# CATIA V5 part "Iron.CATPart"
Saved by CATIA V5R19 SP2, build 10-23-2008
Part number: Part1
Bounding box of the stored display mesh (mm): x -79.133 to 79.133, y -300 to 0, z -3.106 to 127.728
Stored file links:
  C:\Users\SAMAD\Desktop\shape2.CATPart
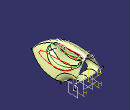
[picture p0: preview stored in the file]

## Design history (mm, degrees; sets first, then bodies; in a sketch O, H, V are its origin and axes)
Body1 (main body)
  Sketch1 on zx-plane, origin (0, 0, 0), H (-1, 0, 0), V (0, 0, 1)
    point P1 (70, 0)
    arc A1 centre (-241.0845, -75.0096) radius 320 from (70, 0) to (20.4309, 109.4076) ccw
    arc A2 centre (0, 95) radius 25 from (20.4309, 109.4076) to (-20.4309, 109.4076) ccw
    point P4 (0, 95)
    arc A3 centre (241.0845, -75.0096) radius 320 from (-20.4309, 109.4076) to (-70, 0) ccw
    point P7 (-70, 0)
    distance A2 H = 120
    distance P1 V = 70
    radius A2 = 25
    radius A1 = 320
    coincidence: P1 H, P7 H, P4 V
    tangency: A2 A1, A3 A2
    symmetry: A1 A3 V
  Sketch2 on yz-plane, origin (0, 0, 0), H (0, 1, 0), V (0, 0, 1)
    spline S1 through (0, 120) (-97.5385, 126.0039) (-300, 0)
    point P1 (0, 120)
    point P2 (-300, 0)
    distance P2 V = 300
    distance P1 H = 120
    coincidence: P1 V, P2 H
  Sketch3 on xy-plane, origin (0, 0, 0), H (1, 0, 0), V (0, 1, 0)
    spline S1 through (70, 0) (71.6167, -27.0715) (76.454, -63.6062) (62.9919, -184.814) (0, -300)
    reference projected point E1 (70, 0) from Sketch1.P7
    reference projected point E2 (0, -300) from Sketch2.P2
    point P1 (70, 0)
    point P2 (0, -300)
    coincidence: P1 H, P2 V, P1 E1, E2 P2
  Symmetry1: ToTransfor Sketch3, Reference yz-plane
  Sketch4 on xy-plane, origin (0, 0, 0), H (1, 0, 0), V (0, 1, 0)
    line L1 (0, 0) -> (0, -300.4665)
    vertical: L1 V
  Plane1: type Offset, RefPlane zx-plane, Offset -214
  Intersect1: ToIntersect1 Plane1, ToIntersect2 Sketch3
  Intersect2: ToIntersect1 Plane1, ToIntersect2 Sketch4
  Intersect3: ToIntersect1 Symmetry1, ToIntersect2 Plane1
  Intersect4: ToIntersect1 Sketch2, ToIntersect2 Plane1
  Sketch5 on Plane1, origin (0, -214, 0), H (-1, 0, 0), V (0, 0, 1)
    point P1 (-50.9944, 0)
    arc A1 centre (133.4907, -45.4446) radius 190 from (-50.9944, 0) to (-12.275, 76.4255) cw
    arc A2 centre (0, 66.1628) radius 16 from (-12.275, 76.4255) to (12.275, 76.4255) cw
    point P4 (0, 66.1628)
    arc A3 centre (-133.4907, -45.4446) radius 190 from (12.275, 76.4255) to (50.9944, 0) cw
    point P7 (50.9944, 0)
    reference projected point E1 (-50.9944, 0) from Intersect1
    reference projected point E2 (50.9944, 0) from Intersect3
    reference projected point E3 (0, 82.1628) from Intersect4
    radius A2 = 16
    radius A1 = 190
    tangency: A2 A1, A3 A2
    coincidence: P1 E1, E2 P7, P4 V, E3 A2
    symmetry: A3 A1 V
  Loft1: Sections (Sketch1; Sketch5), Guides (Sketch3; Sketch2; Symmetry1), SectionCouplingPoints ({coupling CouplingPoints (vertex [element of Sketch1 | element of Sketch1]; vertex [element of Sketch5 | element of Sketch5])}; {coupling CouplingPoints (vertex [element of Sketch1 | element of Sketch1]; vertex [element of Sketch5 | element of Sketch5])})
  Plane2: type Offset, RefPlane yz-plane, Offset 79
  Sketch6 on Plane2, origin (79, 0, 0), H (0, 1, 0), V (0, 0, 1)
    spline S1 through (0, 26.6689) (-20.4626, 28.402) (-45.2977, 19.9352) (-66.558, 0)
    reference projected line E1 (0, 0) -> (-300.4665, 0) from Sketch4
    point P1 (0, 26.6689)
    point P2 (-66.558, 0)
    coincidence: P1 V, P2 E1
  Symmetry2: ToTransfor Sketch6, Reference yz-plane
  Sketch7 on zx-plane, origin (0, 0, 0), H (-1, 0, 0), V (0, 0, 1)
    point P1 (79, 26.6689)
    arc A1 centre (0, 345.3941) radius 328.3698 from (79, 26.6689) to (-79, 26.6689) cw
    point P2 (0, 345.3941)
    point P3 (0, 17.0242)
    point P4 (-79, 26.6689)
    reference projected point E1 (79, 26.6689) from vertex of Symmetry2
    reference projected point E2 (-79, 26.6689) from Sketch6.P1
    coincidence: A1 P3, P3 V, E1 P1, P4 E2, P2 V
  Sweep1: type Unspec, Profile Sketch7, Guide (Sketch6; Symmetry2)
  Split1: ToCut Loft1, Cutting Sweep1
  Split2: ToCut Sweep1, Cutting Split1
  Join1: Elements (Split1; Split2)
  Fillet1: on edge [face of Sweep1 | face of Loft1]
  Sketch8 on yz-plane, origin (0, 0, 0), H (0, 1, 0), V (0, 0, 1)
    arc A1 centre (-36.048, 91.3381) radius 9.9392 from (-37.3936, 101.1858) to (-32.062, 82.2331) cw
    arc A2 centre (-91.0253, 216.9197) radius 147.0277 from (-32.062, 82.2331) to (-152.5397, 83.379) cw
    arc A3 centre (-149.8214, 89.28) radius 6.497 from (-152.5397, 83.379) to (-151.5796, 95.5346) cw
    arc A4 centre (-131.4732, 24.0071) radius 74.2997 from (-151.5796, 95.5346) to (-126.4697, 98.1381) cw
    arc A5 centre (-96.8794, 536.5413) radius 439.4006 from (-126.4697, 98.1381) to (-37.3936, 101.1858) ccw
    tangency: A2 A1, A3 A2, A4 A3, A5 A4, A1 A5
  Sketch9 on Plane2, origin (79, 0, 0), H (0, 1, 0), V (0, 0, 1)
    point P1 (-25.7796, 108.2083)
    arc A1 centre (-23.0053, 94.1541) radius 14.3255 from (-25.7796, 108.2083) to (-15.5229, 81.938) cw
    arc A2 centre (-104.6329, 227.4231) radius 170.6063 from (-15.5229, 81.938) to (-174.8721, 71.9465) cw
    arc A3 centre (-169.91, 82.9303) radius 12.0526 from (-174.8721, 71.9465) to (-174.9117, 93.896) cw
    arc A4 centre (-140.8968, 19.322) radius 81.9652 from (-174.9117, 93.896) to (-135.5148, 101.1103) cw
    arc A5 centre (-107.7294, 523.3524) radius 423.1553 from (-135.5148, 101.1103) to (-25.7796, 108.2083) ccw
    point P11 (-25.7796, 108.2083)
    tangency: A2 A1, A3 A2, A4 A3, A5 A4, A1 A5
    coincidence: P1 P11
    fix: P1
  Symmetry3: ToTransfor Sketch9, Reference yz-plane
  Project1: ToProject Sketch9, Support Fillet1, Direction (1, 0, 0)
  Symmetry4: ToTransfor Project1, Reference yz-plane
  Point1: (0, 0, 0), relative to vertex [face of Project1 | face of Project1]
  Point2: (0, 0, 0), relative to vertex [face of Project1 | face of Project1]
  Point3: (0, 0, 0), relative to vertex [face of Project1 | face of Project1]
  Point4: (0, 0, 0), relative to vertex [face of Project1 | face of Project1]
  Point5: (0, 0, 0), relative to vertex [face of Project1 | face of Project1]
  Point6: (0, 0, 0), relative to vertex [element of Sketch8 | element of Sketch8]
  Point7: (0, 0, 0), relative to vertex [element of Sketch8 | element of Sketch8]
  Point8: (0, 0, 0), relative to vertex [element of Sketch8 | element of Sketch8]
  Point9: (0, 0, 0), relative to vertex [element of Sketch8 | element of Sketch8]
  Point10: (0, 0, 0), relative to vertex [element of Sketch8 | element of Sketch8]
  Point11: (0, 0, 0), relative to vertex [face of Symmetry4 | face of Symmetry4]
  Point12: (0, 0, 0), relative to vertex [face of Symmetry4 | face of Symmetry4]
  Point13: (0, 0, 0), relative to vertex [face of Symmetry4 | face of Symmetry4]
  Point14: (0, 0, 0), relative to vertex [face of Symmetry4 | face of Symmetry4]
  Point15: (0, 0, 0), relative to vertex [face of Symmetry4 | face of Symmetry4]
  Curve1: Elements (Point5; Point6; Point12)
  Curve2: Elements (Point1; Point10; Point11)
  Curve3: Elements (Point4; Point7; Point13)
  Curve4: Elements (Point3; Point8; Point14)
  Loft2: Sections (Project1; Symmetry4), Guides (Curve1; Curve3)
  Split3: ToCut Fillet1, Cutting Project1
  Split4: ToCut Split3, Cutting Symmetry4
  Join2: Elements (Split4; Loft2)
  Fillet2: on edge [face of Loft1 | face of Loft2] (x3); edge [face of Loft2 | face of Loft1]
  Split5: ToCut Fillet2, Cutting yz-plane
  Symmetry5: ToTransfor Split5, Reference yz-plane
  Join3: Elements (Symmetry5; Split5)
